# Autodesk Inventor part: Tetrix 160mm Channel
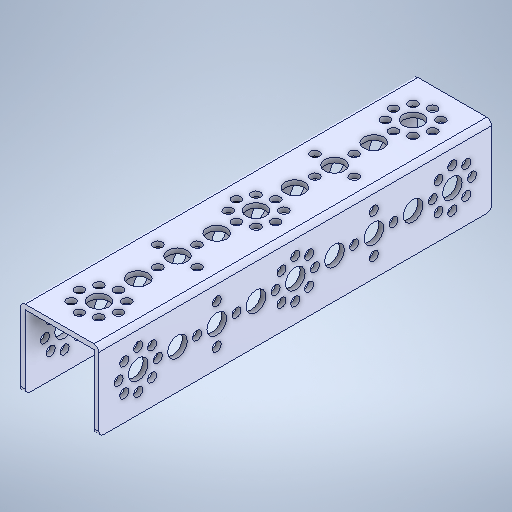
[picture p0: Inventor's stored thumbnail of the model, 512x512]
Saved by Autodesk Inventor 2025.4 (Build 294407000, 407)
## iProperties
Created: 2021-10
Part Number: Tetrix 160mm Channel
Material: Genérico
Document SubType Name: Modeling
Designer: usuario
Density: 1 g/cm^3
Appearance: Valor por defecto
Author: usuario
Sending System: SolidWorks 2016
Last Author: LENOVO
Last Saved: 2021-10-21
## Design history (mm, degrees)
fillet "Fillet1"
node "Plane1"
node "Sólido1"
